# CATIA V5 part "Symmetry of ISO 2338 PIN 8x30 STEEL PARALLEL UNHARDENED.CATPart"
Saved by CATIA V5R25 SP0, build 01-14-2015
Part number: Symmetry of ISO 2338 PIN 8x30 STEEL PARALLEL UNHARDENED
Bounding box of the stored display mesh (mm): x 0 to 30, y -4 to 4, z -3.804 to 3.804
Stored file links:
  D:\feridun18052022montaj\Symmetry of ISO 2338 PIN 8x30 STEEL PARALLEL UNHARDENED.CATPart
  D:\feridun18052022montaj\ISO_2338_8x30_STEEL_PARALLEL_PIN_UNHARDENED.CATPart
  D:\feridun18052022montaj\cektirme.CATProduct
  D:\feridun18052022montaj\03.CATPart
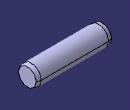
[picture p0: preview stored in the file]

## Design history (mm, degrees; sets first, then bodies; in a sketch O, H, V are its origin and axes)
Body1 (main body)
  Body2 "Body from original PartBody"
    Solid1: linked copy from another document
  Assemble1: tool Body2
